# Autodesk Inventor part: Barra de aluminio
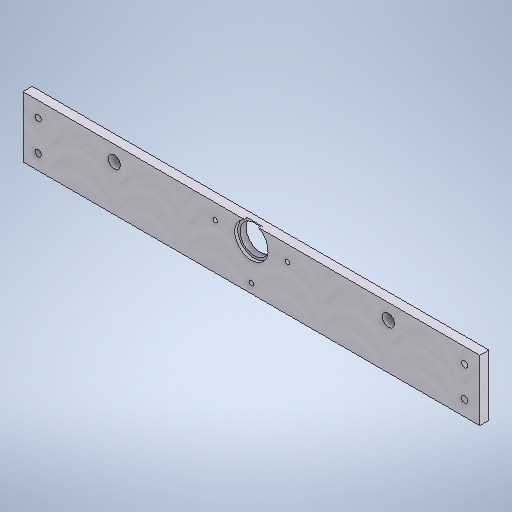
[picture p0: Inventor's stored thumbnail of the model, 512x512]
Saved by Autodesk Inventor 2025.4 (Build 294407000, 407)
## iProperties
Created: 2026-04
Part Number: Barra de aluminio
Material: Aluminum 6061, Welded
Document SubType Name: Modeling
Designer: I11112
Density: 2.7 g/cm^3
Appearance: Weld - Aluminum
Author: I11112
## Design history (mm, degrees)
sketch "Sketch1"
  geometry: L1 (0, 0)-(300, 0); L2 (300, 0)-(300, 40); L3 (300, 40)-(0, 40); L4 (0, 40)-(0, 0); L5 (150, 40)-(150, -16.754); C1 r 4 at (60, 30); C2 r 11 at (150, 30); C3 r 1.5 at (126.2, 30); C4 r 1.5 at (150, 6.2); C5 r 4 at (240, 30); C6 r 1.5 at (173.8, 30); C7 r 1.5 at (150, 6.2); C8 r 2.1 at (10, 30); C9 r 2.1 at (10, 10); C10 r 2.1 at (290, 30); C11 r 2.1 at (290, 10); C12 r 9.5 at (150, 30); 2 further points
  constraints: 12 centre point, 10 end point, 4 symmetric about line, 2 parallel, 1 coincident, 1 horizontal, 1 midpoint, 1 perpendicular, 1 vertical, 5 other
  dimensions: "d0" = 300 distance of L3.end L2.end; "d1" = 40 distance of L2.end L1.end; "d4" = 8 diameter of C1; "d5" = 22 diameter of C2; "d6" = 3 diameter of C3; "d7" = 3 diameter of C4; "d8" = 10 distance from line of L3 C2.centre; "d9" = 10 distance from line of L3 C1.centre; "d10" = 60 distance from line of L4 C1.centre; "d11" = 150 distance from line of L4 C2.centre; "d12" = 10 distance from line of L3 C3.centre; "d14" = 23.8 distance of C2.centre C3.centre; "d15" = 4.2 diameter of C8; "d16" = 4.2 diameter of C9; "d17" = 10 distance from line of L4 C8.centre; "d18" = 10 distance from line of L4 C9.centre; "d19" = 20 distance of C9.centre C8.centre; "d20" = 10 distance from line of L3 C8.centre; "d24" = 23.8 distance of C2.centre C4.centre; "d25" = 19 diameter of C12
extrude "Extrusion1" new body sketch "Sketch1" distance "d2" = 6; taper "d3" = 0 deg
extrude "Extrusion2" join sketch "Sketch1" distance "d26" = 4; taper "d27" = 0 deg
body "Solid1"
